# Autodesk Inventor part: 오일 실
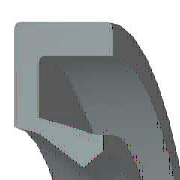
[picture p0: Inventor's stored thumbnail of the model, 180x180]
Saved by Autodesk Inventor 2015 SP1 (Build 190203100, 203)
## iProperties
IsCustomPart: 1
Created: 2012-02
Part Number: 오일 실
Material: 고무
Description: 오일 실 - 스프링 장착, 비스프링, 고무 덮개 G
Document SubType Name: Modeling
Standard: JIS B 2402
Designer: mduedu
Standards Organization: JIS
Language: ko-KR
Size Designation: 20 32 5 A
Categories: <MemberInstance><Categories><Category DisplayName="샤프트 부품" InternalName="7f7aeb1f-a693-4053-b835-cee3144e0d98" Mnemonic="SHFT"><Category DisplayName="실링" Intern
Density: 0.93 g/cm^3
Appearance: 고무 - 검은색 - 버전 1.1
Author: mduedu
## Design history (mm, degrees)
body "Solid1"
revolve "회전1" stored, may be unused: angle "d29" = 360 deg
chamfer "모따기1" distance "d30" = 0.25 (= 0.05 x b); stored, may be unused: second distance "d31" = 0.5 (= 0.1 x b), angle "d39" = 45 deg
chamfer "모따기2" distance "d32" = 0.5 (= 0.1 x b); stored, may be unused: second distance "d33" = 0.25 (= 0.05 x b), angle "d40" = 45 deg
fillet "모깎기1" dims "d34" = 0.25 (= 0.05 x b)
sketch "스케치2"
  geometry: L1 (10.997, -3.438)-(11.297, -5); L2 (10.597, -3.282)-(10.997, -3.438); L3 (10, -1.72)-(10.597, -3.282); L4 (11.091, -1.22)-(10, -1.72); L5 (12.133, -3.75)-(11.091, -1.22); L6 (13.333, -3.75)-(12.133, -3.75); L7 (14.667, -1.25)-(13.333, -3.75); L8 (14.667, 0)-(14.667, -1.25); L9 (16, 0)-(14.667, 0); L10 (16, -5)-(16, 0); L11 (11.297, -5)-(16, -5); L12 (0, -9.6)-(0, 1.6) reference; L13 (28, 0)-(14, 0) reference
  constraints: 22 end point, 3 horizontal, 2 vertical
  dimensions: "d2" = 5 distance of L10.start L9.start (= b); "d4" = 1.25 vertical distance of L5.start L1.end (= 0.25 x b); "d6" = 1.33333 distance of L9.start L8.start (= 0.111111 x dd - 0.111111 x Diam); "d8" = 1.25 distance of L8.start L7.start (= 0.25 x b); "d10" = 1.33333 horizontal distance of L7.start L6.start (= 0.111111 x dd - 0.111111 x Diam); "d12" = 1.21951 vertical distance of L9.start L4.start (= 0.243902 x b); "d14" = 1.09091 horizontal distance of L4.start L3.start (= 0.0909091 x dd - 0.0909091 x Diam); "d16" = 0.5 vertical distance of L4.start L3.start (= 0.1 x b); "d18" = 1.2 distance of L6.start L5.start (= 0.1 x dd - 0.1 x Diam); "d20" = 1.5625 vertical distance of L3.start L2.start (= 0.3125 x b); "d22" = 0.59701 horizontal distance of L3.start L2.start (= 0.0497512 x dd - 0.0497512 x Diam); "d24" = 0.3 horizontal distance of L1.start L1.end (= 0.025 x dd - 0.025 x Diam); "d26" = 1.5625 vertical distance of L1.start L1.end (= 0.3125 x b); "d28" = 0.4 horizontal distance of L2.start L1.start (= 0.0333333 x dd - 0.0333333 x Diam); "d35" = 0 distance between parallel lines of L13 L9; "d36" = 16 distance between parallel lines of L12 L10 (= 0.5 x dd); "d37" = 10 distance from line of L12 L3.start (= 0.5 x Diam)
other parameters: "dd" = 32 [user parameter; used in 8 equation terms], "b" = 5 [user parameter; used in 12 equation terms], "d1" = 8 (derived), "d3" = 2 (derived), "d5" = 2.22222 (derived), "d7" = 2 (derived), "d9" = 2.22222 (derived), "d11" = 1.95122 (derived), "d13" = 1.81818 (derived), "d15" = 0.8 (derived), "d17" = 2 (derived), "d19" = 2.5 (derived), "d21" = 0.99502 (derived), "d23" = 0.5 (derived), "d25" = 2.5 (derived), "d27" = 0.66667 (derived), "d38" = 0
